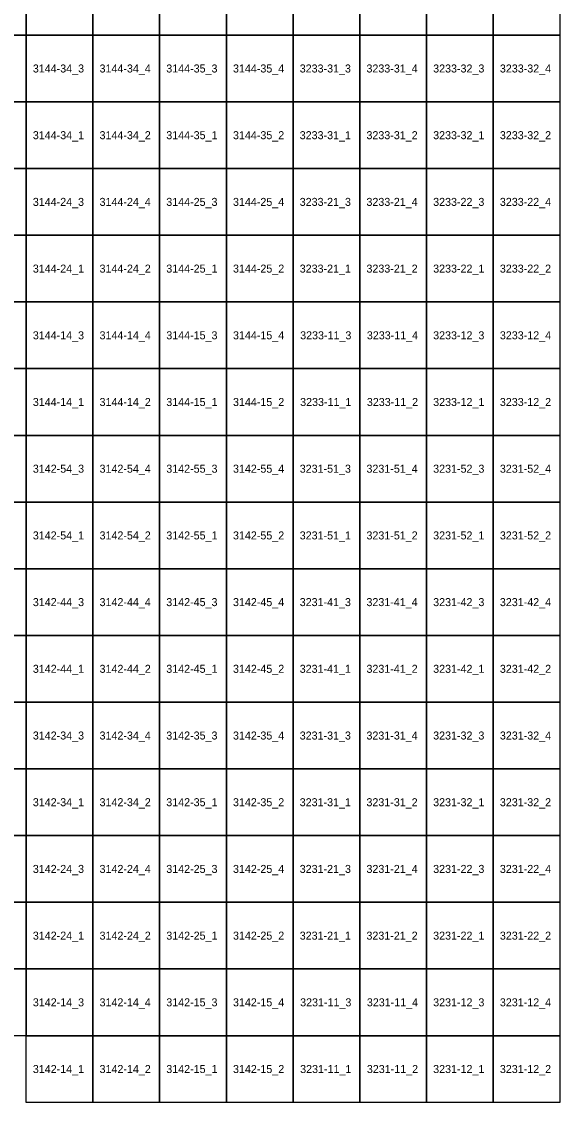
# Model space of a CAD drawing. Extents: x 312500 to 765000, y 172500 to 440000.
# Drawn here: x 389827 to 409827, y 250000 to 290507 of the extents above; entities that cross this region are included whole.
import ezdxf

# ---------------------------------------------------------------- set-up
doc = ezdxf.new("R2010")
doc.units = 0
doc.layers.add('Topo5_ramis_TKS2025', color=7, linetype='Continuous')
doc.layers.add('Topo5_ramis_TKS2025_Nr', color=7, linetype='Continuous')

msp = doc.modelspace()

# ---------------------------------------------------------------- linework, layer by layer
at = {"layer": 'Topo5_ramis_TKS2025'}
for points in [[(387500, 290000), (387500, 292500), (390000, 292500), (390000, 290000), (387500, 290000)], [(390000, 290000), (390000, 292500), (392500, 292500), (392500, 290000), (390000, 290000)], [(392500, 290000), (392500, 292500), (395000, 292500), (395000, 290000), (392500, 290000)], [(395000, 290000), (395000, 292500), (397500, 292500), (397500, 290000), (395000, 290000)], [(397500, 290000), (397500, 292500), (400000, 292500), (400000, 290000), (397500, 290000)], [(400000, 290000), (400000, 292500), (402500, 292500), (402500, 290000), (400000, 290000)], [(402500, 290000), (402500, 292500), (405000, 292500), (405000, 290000), (402500, 290000)], [(405000, 290000), (405000, 292500), (407500, 292500), (407500, 290000), (405000, 290000)], [(407500, 290000), (407500, 292500), (410000, 292500), (410000, 290000), (407500, 290000)], [(387500, 287500), (387500, 290000), (390000, 290000), (390000, 287500), (387500, 287500)], [(390000, 287500), (390000, 290000), (392500, 290000), (392500, 287500), (390000, 287500)], [(392500, 287500), (392500, 290000), (395000, 290000), (395000, 287500), (392500, 287500)], [(395000, 287500), (395000, 290000), (397500, 290000), (397500, 287500), (395000, 287500)], [(397500, 287500), (397500, 290000), (400000, 290000), (400000, 287500), (397500, 287500)], [(400000, 287500), (400000, 290000), (402500, 290000), (402500, 287500), (400000, 287500)], [(402500, 287500), (402500, 290000), (405000, 290000), (405000, 287500), (402500, 287500)], [(405000, 287500), (405000, 290000), (407500, 290000), (407500, 287500), (405000, 287500)], [(407500, 287500), (407500, 290000), (410000, 290000), (410000, 287500), (407500, 287500)], [(387500, 285000), (387500, 287500), (390000, 287500), (390000, 285000), (387500, 285000)], [(390000, 285000), (390000, 287500), (392500, 287500), (392500, 285000), (390000, 285000)], [(392500, 285000), (392500, 287500), (395000, 287500), (395000, 285000), (392500, 285000)], [(395000, 285000), (395000, 287500), (397500, 287500), (397500, 285000), (395000, 285000)], [(397500, 285000), (397500, 287500), (400000, 287500), (400000, 285000), (397500, 285000)], [(400000, 285000), (400000, 287500), (402500, 287500), (402500, 285000), (400000, 285000)], [(402500, 285000), (402500, 287500), (405000, 287500), (405000, 285000), (402500, 285000)], [(405000, 285000), (405000, 287500), (407500, 287500), (407500, 285000), (405000, 285000)], [(407500, 285000), (407500, 287500), (410000, 287500), (410000, 285000), (407500, 285000)], [(387500, 282500), (387500, 285000), (390000, 285000), (390000, 282500), (387500, 282500)], [(390000, 282500), (390000, 285000), (392500, 285000), (392500, 282500), (390000, 282500)], [(392500, 282500), (392500, 285000), (395000, 285000), (395000, 282500), (392500, 282500)], [(395000, 282500), (395000, 285000), (397500, 285000), (397500, 282500), (395000, 282500)], [(397500, 282500), (397500, 285000), (400000, 285000), (400000, 282500), (397500, 282500)], [(400000, 282500), (400000, 285000), (402500, 285000), (402500, 282500), (400000, 282500)], [(402500, 282500), (402500, 285000), (405000, 285000), (405000, 282500), (402500, 282500)], [(405000, 282500), (405000, 285000), (407500, 285000), (407500, 282500), (405000, 282500)], [(407500, 282500), (407500, 285000), (410000, 285000), (410000, 282500), (407500, 282500)], [(387500, 280000), (387500, 282500), (390000, 282500), (390000, 280000), (387500, 280000)], [(390000, 280000), (390000, 282500), (392500, 282500), (392500, 280000), (390000, 280000)], [(392500, 280000), (392500, 282500), (395000, 282500), (395000, 280000), (392500, 280000)], [(395000, 280000), (395000, 282500), (397500, 282500), (397500, 280000), (395000, 280000)], [(397500, 280000), (397500, 282500), (400000, 282500), (400000, 280000), (397500, 280000)], [(400000, 280000), (400000, 282500), (402500, 282500), (402500, 280000), (400000, 280000)], [(402500, 280000), (402500, 282500), (405000, 282500), (405000, 280000), (402500, 280000)], [(405000, 280000), (405000, 282500), (407500, 282500), (407500, 280000), (405000, 280000)], [(407500, 280000), (407500, 282500), (410000, 282500), (410000, 280000), (407500, 280000)], [(387500, 277500), (387500, 280000), (390000, 280000), (390000, 277500), (387500, 277500)], [(390000, 277500), (390000, 280000), (392500, 280000), (392500, 277500), (390000, 277500)], [(392500, 277500), (392500, 280000), (395000, 280000), (395000, 277500), (392500, 277500)], [(395000, 277500), (395000, 280000), (397500, 280000), (397500, 277500), (395000, 277500)], [(397500, 277500), (397500, 280000), (400000, 280000), (400000, 277500), (397500, 277500)], [(400000, 277500), (400000, 280000), (402500, 280000), (402500, 277500), (400000, 277500)], [(402500, 277500), (402500, 280000), (405000, 280000), (405000, 277500), (402500, 277500)], [(405000, 277500), (405000, 280000), (407500, 280000), (407500, 277500), (405000, 277500)], [(407500, 277500), (407500, 280000), (410000, 280000), (410000, 277500), (407500, 277500)], [(387500, 275000), (387500, 277500), (390000, 277500), (390000, 275000), (387500, 275000)], [(390000, 275000), (390000, 277500), (392500, 277500), (392500, 275000), (390000, 275000)], [(392500, 275000), (392500, 277500), (395000, 277500), (395000, 275000), (392500, 275000)], [(395000, 275000), (395000, 277500), (397500, 277500), (397500, 275000), (395000, 275000)], [(397500, 275000), (397500, 277500), (400000, 277500), (400000, 275000), (397500, 275000)], [(400000, 275000), (400000, 277500), (402500, 277500), (402500, 275000), (400000, 275000)], [(402500, 275000), (402500, 277500), (405000, 277500), (405000, 275000), (402500, 275000)], [(405000, 275000), (405000, 277500), (407500, 277500), (407500, 275000), (405000, 275000)], [(407500, 275000), (407500, 277500), (410000, 277500), (410000, 275000), (407500, 275000)], [(387500, 272500), (387500, 275000), (390000, 275000), (390000, 272500), (387500, 272500)], [(390000, 272500), (390000, 275000), (392500, 275000), (392500, 272500), (390000, 272500)], [(392500, 272500), (392500, 275000), (395000, 275000), (395000, 272500), (392500, 272500)], [(395000, 272500), (395000, 275000), (397500, 275000), (397500, 272500), (395000, 272500)], [(397500, 272500), (397500, 275000), (400000, 275000), (400000, 272500), (397500, 272500)], [(400000, 272500), (400000, 275000), (402500, 275000), (402500, 272500), (400000, 272500)], [(402500, 272500), (402500, 275000), (405000, 275000), (405000, 272500), (402500, 272500)], [(405000, 272500), (405000, 275000), (407500, 275000), (407500, 272500), (405000, 272500)], [(407500, 272500), (407500, 275000), (410000, 275000), (410000, 272500), (407500, 272500)], [(387500, 270000), (387500, 272500), (390000, 272500), (390000, 270000), (387500, 270000)], [(390000, 270000), (390000, 272500), (392500, 272500), (392500, 270000), (390000, 270000)], [(392500, 270000), (392500, 272500), (395000, 272500), (395000, 270000), (392500, 270000)], [(395000, 270000), (395000, 272500), (397500, 272500), (397500, 270000), (395000, 270000)], [(397500, 270000), (397500, 272500), (400000, 272500), (400000, 270000), (397500, 270000)], [(400000, 270000), (400000, 272500), (402500, 272500), (402500, 270000), (400000, 270000)], [(402500, 270000), (402500, 272500), (405000, 272500), (405000, 270000), (402500, 270000)], [(405000, 270000), (405000, 272500), (407500, 272500), (407500, 270000), (405000, 270000)], [(407500, 270000), (407500, 272500), (410000, 272500), (410000, 270000), (407500, 270000)], [(387500, 267500), (387500, 270000), (390000, 270000), (390000, 267500), (387500, 267500)], [(390000, 267500), (390000, 270000), (392500, 270000), (392500, 267500), (390000, 267500)], [(392500, 267500), (392500, 270000), (395000, 270000), (395000, 267500), (392500, 267500)], [(395000, 267500), (395000, 270000), (397500, 270000), (397500, 267500), (395000, 267500)], [(397500, 267500), (397500, 270000), (400000, 270000), (400000, 267500), (397500, 267500)], [(400000, 267500), (400000, 270000), (402500, 270000), (402500, 267500), (400000, 267500)], [(402500, 267500), (402500, 270000), (405000, 270000), (405000, 267500), (402500, 267500)], [(405000, 267500), (405000, 270000), (407500, 270000), (407500, 267500), (405000, 267500)], [(407500, 267500), (407500, 270000), (410000, 270000), (410000, 267500), (407500, 267500)], [(387500, 265000), (387500, 267500), (390000, 267500), (390000, 265000), (387500, 265000)], [(390000, 265000), (390000, 267500), (392500, 267500), (392500, 265000), (390000, 265000)], [(392500, 265000), (392500, 267500), (395000, 267500), (395000, 265000), (392500, 265000)], [(395000, 265000), (395000, 267500), (397500, 267500), (397500, 265000), (395000, 265000)], [(397500, 265000), (397500, 267500), (400000, 267500), (400000, 265000), (397500, 265000)], [(400000, 265000), (400000, 267500), (402500, 267500), (402500, 265000), (400000, 265000)], [(402500, 265000), (402500, 267500), (405000, 267500), (405000, 265000), (402500, 265000)], [(405000, 265000), (405000, 267500), (407500, 267500), (407500, 265000), (405000, 265000)], [(407500, 265000), (407500, 267500), (410000, 267500), (410000, 265000), (407500, 265000)], [(387500, 262500), (387500, 265000), (390000, 265000), (390000, 262500), (387500, 262500)], [(390000, 262500), (390000, 265000), (392500, 265000), (392500, 262500), (390000, 262500)], [(392500, 262500), (392500, 265000), (395000, 265000), (395000, 262500), (392500, 262500)], [(395000, 262500), (395000, 265000), (397500, 265000), (397500, 262500), (395000, 262500)], [(397500, 262500), (397500, 265000), (400000, 265000), (400000, 262500), (397500, 262500)], [(400000, 262500), (400000, 265000), (402500, 265000), (402500, 262500), (400000, 262500)], [(402500, 262500), (402500, 265000), (405000, 265000), (405000, 262500), (402500, 262500)], [(405000, 262500), (405000, 265000), (407500, 265000), (407500, 262500), (405000, 262500)], [(407500, 262500), (407500, 265000), (410000, 265000), (410000, 262500), (407500, 262500)], [(387500, 260000), (387500, 262500), (390000, 262500), (390000, 260000), (387500, 260000)], [(390000, 260000), (390000, 262500), (392500, 262500), (392500, 260000), (390000, 260000)], [(392500, 260000), (392500, 262500), (395000, 262500), (395000, 260000), (392500, 260000)], [(395000, 260000), (395000, 262500), (397500, 262500), (397500, 260000), (395000, 260000)], [(397500, 260000), (397500, 262500), (400000, 262500), (400000, 260000), (397500, 260000)], [(400000, 260000), (400000, 262500), (402500, 262500), (402500, 260000), (400000, 260000)], [(402500, 260000), (402500, 262500), (405000, 262500), (405000, 260000), (402500, 260000)], [(405000, 260000), (405000, 262500), (407500, 262500), (407500, 260000), (405000, 260000)], [(407500, 260000), (407500, 262500), (410000, 262500), (410000, 260000), (407500, 260000)], [(387500, 257500), (387500, 260000), (390000, 260000), (390000, 257500), (387500, 257500)], [(390000, 257500), (390000, 260000), (392500, 260000), (392500, 257500), (390000, 257500)], [(392500, 257500), (392500, 260000), (395000, 260000), (395000, 257500), (392500, 257500)], [(395000, 257500), (395000, 260000), (397500, 260000), (397500, 257500), (395000, 257500)], [(397500, 257500), (397500, 260000), (400000, 260000), (400000, 257500), (397500, 257500)], [(400000, 257500), (400000, 260000), (402500, 260000), (402500, 257500), (400000, 257500)], [(402500, 257500), (402500, 260000), (405000, 260000), (405000, 257500), (402500, 257500)], [(405000, 257500), (405000, 260000), (407500, 260000), (407500, 257500), (405000, 257500)], [(407500, 257500), (407500, 260000), (410000, 260000), (410000, 257500), (407500, 257500)], [(387500, 255000), (387500, 257500), (390000, 257500), (390000, 255000), (387500, 255000)], [(390000, 255000), (390000, 257500), (392500, 257500), (392500, 255000), (390000, 255000)], [(392500, 255000), (392500, 257500), (395000, 257500), (395000, 255000), (392500, 255000)], [(395000, 255000), (395000, 257500), (397500, 257500), (397500, 255000), (395000, 255000)], [(397500, 255000), (397500, 257500), (400000, 257500), (400000, 255000), (397500, 255000)], [(400000, 255000), (400000, 257500), (402500, 257500), (402500, 255000), (400000, 255000)], [(402500, 255000), (402500, 257500), (405000, 257500), (405000, 255000), (402500, 255000)], [(405000, 255000), (405000, 257500), (407500, 257500), (407500, 255000), (405000, 255000)], [(407500, 255000), (407500, 257500), (410000, 257500), (410000, 255000), (407500, 255000)], [(387500, 252500), (387500, 255000), (390000, 255000), (390000, 252500), (387500, 252500)], [(390000, 252500), (390000, 255000), (392500, 255000), (392500, 252500), (390000, 252500)], [(392500, 252500), (392500, 255000), (395000, 255000), (395000, 252500), (392500, 252500)], [(395000, 252500), (395000, 255000), (397500, 255000), (397500, 252500), (395000, 252500)], [(397500, 252500), (397500, 255000), (400000, 255000), (400000, 252500), (397500, 252500)], [(400000, 252500), (400000, 255000), (402500, 255000), (402500, 252500), (400000, 252500)], [(402500, 252500), (402500, 255000), (405000, 255000), (405000, 252500), (402500, 252500)], [(405000, 252500), (405000, 255000), (407500, 255000), (407500, 252500), (405000, 252500)], [(407500, 252500), (407500, 255000), (410000, 255000), (410000, 252500), (407500, 252500)], [(390000, 250000), (390000, 252500), (392500, 252500), (392500, 250000), (390000, 250000)], [(392500, 250000), (392500, 252500), (395000, 252500), (395000, 250000), (392500, 250000)], [(395000, 250000), (395000, 252500), (397500, 252500), (397500, 250000), (395000, 250000)], [(397500, 250000), (397500, 252500), (400000, 252500), (400000, 250000), (397500, 250000)], [(400000, 250000), (400000, 252500), (402500, 252500), (402500, 250000), (400000, 250000)], [(402500, 250000), (402500, 252500), (405000, 252500), (405000, 250000), (402500, 250000)], [(405000, 250000), (405000, 252500), (407500, 252500), (407500, 250000), (405000, 250000)], [(407500, 250000), (407500, 252500), (410000, 252500), (410000, 250000), (407500, 250000)]]:
    msp.add_lwpolyline(points, dxfattribs=at)

# ---------------------------------------------------------------- texts
at = {"layer": 'Topo5_ramis_TKS2025_Nr'}
for s, p in [('3144-34_3', (390248, 288600)), ('3144-34_4', (392748, 288600)), ('3144-35_3', (395248, 288600)), ('3144-35_4', (397748, 288600)), ('3233-31_3', (400248, 288600)), ('3233-31_4', (402748, 288600)), ('3233-32_3', (405248, 288600)), ('3233-32_4', (407748, 288600)), ('3144-34_1', (390248, 286100)), ('3144-34_2', (392748, 286100)), ('3144-35_1', (395248, 286100)), ('3144-35_2', (397748, 286100)), ('3233-31_1', (400248, 286100)), ('3233-31_2', (402748, 286100)), ('3233-32_1', (405248, 286100)), ('3233-32_2', (407748, 286100)), ('3144-24_3', (390248, 283600)), ('3144-24_4', (392748, 283600)), ('3144-25_3', (395248, 283600)), ('3144-25_4', (397748, 283600)), ('3233-21_3', (400248, 283600)), ('3233-21_4', (402748, 283600)), ('3233-22_3', (405248, 283600)), ('3233-22_4', (407748, 283600)), ('3144-24_1', (390248, 281100)), ('3144-24_2', (392748, 281100)), ('3144-25_1', (395248, 281100)), ('3144-25_2', (397748, 281100)), ('3233-21_1', (400248, 281100)), ('3233-21_2', (402748, 281100)), ('3233-22_1', (405248, 281100)), ('3233-22_2', (407748, 281100)), ('3144-14_3', (390248, 278600)), ('3144-14_4', (392748, 278600)), ('3144-15_3', (395248, 278600)), ('3144-15_4', (397748, 278600)), ('3233-11_3', (400264, 278600)), ('3233-11_4', (402764, 278600)), ('3233-12_3', (405248, 278600)), ('3233-12_4', (407748, 278600)), ('3144-14_1', (390248, 276100)), ('3144-14_2', (392748, 276100)), ('3144-15_1', (395248, 276100)), ('3144-15_2', (397748, 276100)), ('3233-11_1', (400264, 276100)), ('3233-11_2', (402764, 276100)), ('3233-12_1', (405248, 276100)), ('3233-12_2', (407748, 276100)), ('3142-54_3', (390248, 273600)), ('3142-54_4', (392748, 273600)), ('3142-55_3', (395248, 273600)), ('3142-55_4', (397748, 273600)), ('3231-51_3', (400248, 273600)), ('3231-51_4', (402748, 273600)), ('3231-52_3', (405248, 273600)), ('3231-52_4', (407748, 273600)), ('3142-54_1', (390248, 271100)), ('3142-54_2', (392748, 271100)), ('3142-55_1', (395248, 271100)), ('3142-55_2', (397748, 271100)), ('3231-51_1', (400248, 271100)), ('3231-51_2', (402748, 271100)), ('3231-52_1', (405248, 271100)), ('3231-52_2', (407748, 271100)), ('3142-44_3', (390248, 268600)), ('3142-44_4', (392748, 268600)), ('3142-45_3', (395248, 268600)), ('3142-45_4', (397748, 268600)), ('3231-41_3', (400248, 268600)), ('3231-41_4', (402748, 268600)), ('3231-42_3', (405248, 268600)), ('3231-42_4', (407748, 268600)), ('3142-44_1', (390248, 266100)), ('3142-44_2', (392748, 266100)), ('3142-45_1', (395248, 266100)), ('3142-45_2', (397748, 266100)), ('3231-41_1', (400248, 266100)), ('3231-41_2', (402748, 266100)), ('3231-42_1', (405248, 266100)), ('3231-42_2', (407748, 266100)), ('3142-34_3', (390248, 263600)), ('3142-34_4', (392748, 263600)), ('3142-35_3', (395248, 263600)), ('3142-35_4', (397748, 263600)), ('3231-31_3', (400248, 263600)), ('3231-31_4', (402748, 263600)), ('3231-32_3', (405248, 263600)), ('3231-32_4', (407748, 263600)), ('3142-34_1', (390248, 261100)), ('3142-34_2', (392748, 261100)), ('3142-35_1', (395248, 261100)), ('3142-35_2', (397748, 261100)), ('3231-31_1', (400248, 261100)), ('3231-31_2', (402748, 261100)), ('3231-32_1', (405248, 261100)), ('3231-32_2', (407748, 261100)), ('3142-24_3', (390248, 258600)), ('3142-24_4', (392748, 258600)), ('3142-25_3', (395248, 258600)), ('3142-25_4', (397748, 258600)), ('3231-21_3', (400248, 258600)), ('3231-21_4', (402748, 258600)), ('3231-22_3', (405248, 258600)), ('3231-22_4', (407748, 258600)), ('3142-24_1', (390248, 256100)), ('3142-24_2', (392748, 256100)), ('3142-25_1', (395248, 256100)), ('3142-25_2', (397748, 256100)), ('3231-21_1', (400248, 256100)), ('3231-21_2', (402748, 256100)), ('3231-22_1', (405248, 256100)), ('3231-22_2', (407748, 256100)), ('3142-14_3', (390248, 253600)), ('3142-14_4', (392748, 253600)), ('3142-15_3', (395248, 253600)), ('3142-15_4', (397748, 253600)), ('3231-11_3', (400264, 253600)), ('3231-11_4', (402764, 253600)), ('3231-12_3', (405248, 253600)), ('3231-12_4', (407748, 253600)), ('3142-14_1', (390248, 251100)), ('3142-14_2', (392748, 251100)), ('3142-15_1', (395248, 251100)), ('3142-15_2', (397748, 251100)), ('3231-11_1', (400264, 251100)), ('3231-11_2', (402764, 251100)), ('3231-12_1', (405248, 251100)), ('3231-12_2', (407748, 251100))]:
    msp.add_text(s, height=300, dxfattribs=at).set_placement(p)

doc.saveas('drawing.dxf')
